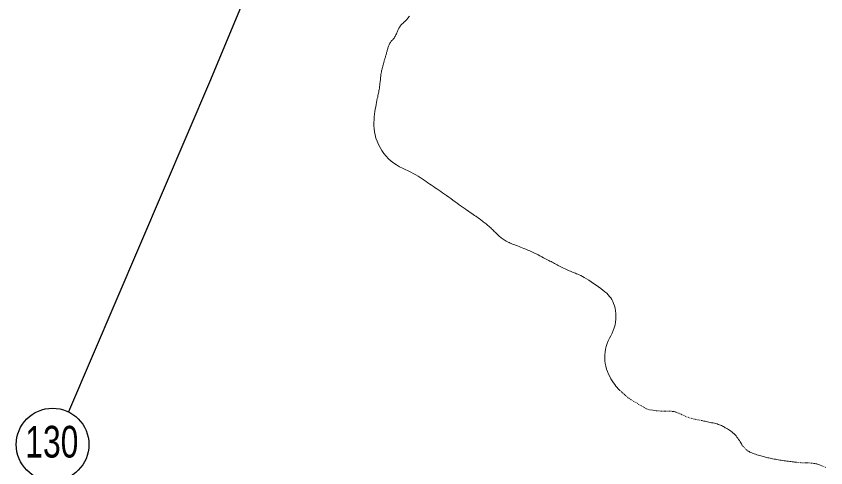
# Model space of a CAD drawing. Extents: x 553962 to 842807, y 8883888 to 9032388.
# Drawn here: x 601794 to 603582, y 8911220 to 8912217 of the extents above; entities that cross this region are included whole.
import ezdxf
from ezdxf.enums import TextEntityAlignment as Align

# ---------------------------------------------------------------- set-up
doc = ezdxf.new("R2010")
doc.units = 0
doc.header["$LTSCALE"] = 200
doc.layers.add('6', color=7, linetype='Continuous', lineweight=13)

msp = doc.modelspace()

# ---------------------------------------------------------------- linework, layer by layer
at = {"layer": '6'}
for p, q in [((602659.5, 8912214.1), (602658.3, 8912212.5)), ((602642.5, 8912196.5), (602641.7, 8912195.4)), ((602642.5, 8912196.5), (602643.4, 8912197.5)), ((602644.3, 8912198.6), (602643.4, 8912197.5)), ((602644.3, 8912198.6), (602645.3, 8912199.6)), ((602646.3, 8912200.5), (602645.3, 8912199.6)), ((602646.3, 8912200.5), (602647.3, 8912201.5)), ((602648.3, 8912202.3), (602647.3, 8912201.5)), ((602648.3, 8912202.3), (602649.2, 8912203.2)), ((602650.2, 8912204), (602649.2, 8912203.2)), ((602650.2, 8912204), (602651.1, 8912204.8)), ((602651.9, 8912205.5), (602651.1, 8912204.8)), ((602651.9, 8912205.5), (602652.7, 8912206.2)), ((602653.5, 8912207), (602652.7, 8912206.2)), ((602653.5, 8912207), (602654.4, 8912207.8)), ((602655.2, 8912208.8), (602654.4, 8912207.8)), ((602655.2, 8912208.8), (602656.2, 8912209.8)), ((602657.2, 8912211.1), (602656.2, 8912209.8)), ((602657.2, 8912211.1), (602658.3, 8912212.5)), ((602636.8, 8912186.1), (602636, 8912184.3)), ((602636.8, 8912186.1), (602637.5, 8912187.8)), ((602638.2, 8912189.3), (602637.5, 8912187.8)), ((602638.2, 8912189.3), (602638.9, 8912190.7)), ((602639.6, 8912192), (602638.9, 8912190.7)), ((602639.6, 8912192), (602640.2, 8912193.2)), ((602641, 8912194.3), (602640.2, 8912193.2)), ((602641, 8912194.3), (602641.7, 8912195.4)), ((602620.1, 8912159.3), (602621.1, 8912160.7)), ((602622.2, 8912162.1), (602621.1, 8912160.7)), ((602622.2, 8912162.1), (602623.4, 8912163.4)), ((602624.6, 8912164.8), (602623.4, 8912163.4)), ((602624.6, 8912164.8), (602625.8, 8912166.2)), ((602627, 8912167.6), (602625.8, 8912166.2)), ((602613.2, 8912142), (602613.7, 8912143.7)), ((602614.2, 8912145.5), (602613.7, 8912143.7)), ((602614.2, 8912145.5), (602614.7, 8912147.3)), ((602615.3, 8912149.1), (602614.7, 8912147.3)), ((602615.3, 8912149.1), (602615.9, 8912150.9)), ((602616.6, 8912152.7), (602615.9, 8912150.9)), ((602616.6, 8912152.7), (602617.4, 8912154.4)), ((602618.2, 8912156.1), (602617.4, 8912154.4)), ((602618.2, 8912156.1), (602619.1, 8912157.7)), ((602620.1, 8912159.3), (602619.1, 8912157.7)), ((602608.6, 8912125.6), (602608.1, 8912124.1)), ((602608.6, 8912125.6), (602609.2, 8912127.2)), ((602609.7, 8912128.8), (602609.2, 8912127.2)), ((602609.7, 8912128.8), (602610.2, 8912130.4)), ((602610.6, 8912132), (602610.2, 8912130.4)), ((602610.6, 8912132), (602611.1, 8912133.6)), ((602611.5, 8912135.3), (602611.1, 8912133.6)), ((602611.5, 8912135.3), (602611.9, 8912136.9)), ((602612.3, 8912138.6), (602611.9, 8912136.9)), ((602612.3, 8912138.6), (602612.8, 8912140.3)), ((602613.2, 8912142), (602612.8, 8912140.3)), ((602603.4, 8912106.7), (602603, 8912105.2)), ((602603.4, 8912106.7), (602603.8, 8912108.1)), ((602604.2, 8912109.7), (602603.8, 8912108.1)), ((602604.2, 8912109.7), (602604.6, 8912111.2)), ((602605, 8912112.8), (602604.6, 8912111.2)), ((602605, 8912112.8), (602605.4, 8912114.4)), ((602605.8, 8912116), (602605.4, 8912114.4)), ((602605.8, 8912116), (602606.2, 8912117.7)), ((602606.7, 8912119.3), (602606.2, 8912117.7)), ((602606.7, 8912119.3), (602607.1, 8912120.9)), ((602607.6, 8912122.5), (602607.1, 8912120.9)), ((602607.6, 8912122.5), (602608.1, 8912124.1)), ((602601.7, 8912100.7), (602601.3, 8912098.8)), ((602601.7, 8912100.7), (602602.2, 8912102.3)), ((602602.6, 8912103.8), (602602.2, 8912102.3)), ((602602.6, 8912103.8), (602603, 8912105.2)), ((603131, 8911387.2), (603129.6, 8911388.4)), ((603133.4, 8911385.2), (603132.3, 8911386.2)), ((603135.6, 8911383.3), (603134.6, 8911384.2)), ((603137.8, 8911381.3), (603136.7, 8911382.3)), ((603140, 8911379.3), (603138.9, 8911380.3)), ((603142.6, 8911377.2), (603141.3, 8911378.3)), ((603145.4, 8911374.9), (603144, 8911376.1)), ((603148.5, 8911372.6), (603147, 8911373.8)), ((603151.7, 8911370.4), (603150.1, 8911371.5)), ((603154.8, 8911368.4), (603153.2, 8911369.4)), ((603157.8, 8911366.6), (603156.3, 8911367.5)), ((603160.7, 8911364.9), (603159.2, 8911365.7)), ((603163.5, 8911363.3), (603162.1, 8911364.1)), ((603166.3, 8911361.7), (603164.9, 8911362.5)), ((603169, 8911360.1), (603167.6, 8911360.9)), ((603171.7, 8911358.5), (603170.3, 8911359.3)), ((603174.4, 8911356.9), (603173, 8911357.7)), ((603177, 8911355.3), (603175.7, 8911356.1)), ((603179.7, 8911353.8), (603178.3, 8911354.6)), ((603182.2, 8911352.4), (603180.9, 8911353.1)), ((603184.6, 8911351.1), (603183.4, 8911351.7)), ((603186.8, 8911350.1), (603185.8, 8911350.6)), ((603188.9, 8911349.3), (603187.9, 8911349.7)), ((603191, 8911348.7), (603190, 8911349)), ((603193.3, 8911348.2), (603192.2, 8911348.4)), ((603196, 8911347.7), (603194.6, 8911347.9)), ((603199.1, 8911347.2), (603197.5, 8911347.5)), ((603202.3, 8911346.8), (603200.7, 8911347)), ((603205.5, 8911346.4), (603203.9, 8911346.6)), ((603208.6, 8911346), (603207.1, 8911346.2)), ((603211.6, 8911345.7), (603210.1, 8911345.9)), ((603214.3, 8911345.5), (603213, 8911345.6)), ((603217, 8911345.3), (603215.6, 8911345.4)), ((603219.5, 8911345.2), (603218.2, 8911345.2)), ((603222, 8911345.1), (603220.8, 8911345.1)), ((603224.5, 8911345), (603223.2, 8911345.1)), ((603226.9, 8911345), (603225.7, 8911345)), ((603229.2, 8911345), (603228, 8911345)), ((603231.5, 8911345), (603230.3, 8911345)), ((603233.7, 8911344.9), (603232.6, 8911344.9)), ((603235.8, 8911344.9), (603234.8, 8911344.9)), ((603237.8, 8911344.9), (603236.8, 8911344.9)), ((603240.7, 8911344.8), (603239.7, 8911344.9)), ((603243.6, 8911344.6), (603242.6, 8911344.7)), ((603245.8, 8911344.2), (603244.7, 8911344.4)), ((603248, 8911343.7), (603246.9, 8911344)), ((603250.4, 8911343), (603249.2, 8911343.4)), ((603252.9, 8911342.1), (603251.6, 8911342.6)), ((603255.5, 8911341.1), (603254.2, 8911341.6)), ((603258.1, 8911339.9), (603256.8, 8911340.5)), ((603263.3, 8911338.7), (603259.4, 8911339.3)), ((603263.5, 8911337.3), (603262.1, 8911338)), ((603266.4, 8911336), (603265, 8911336.7)), ((603269.4, 8911334.6), (603267.9, 8911335.3)), ((603272.5, 8911333.3), (603271, 8911334)), ((603275.8, 8911332.1), (603274.1, 8911332.7)), ((603279.1, 8911330.9), (603277.4, 8911331.5)), ((603282.5, 8911329.9), (603280.8, 8911330.4)), ((603285.8, 8911329), (603284.2, 8911329.4)), ((603289.1, 8911328.2), (603287.5, 8911328.6)), ((603292.1, 8911327.5), (603290.6, 8911327.8)), ((603294.9, 8911326.9), (603293.5, 8911327.2)), ((603297.7, 8911326.3), (603296.3, 8911326.6)), ((603300.8, 8911325.7), (603299.2, 8911326)), ((603304.2, 8911325), (603302.5, 8911325.3)), ((603308.2, 8911324.2), (603306.2, 8911324.6)), ((603400, 8911266.3), (603398.8, 8911267.7)), ((603402.3, 8911263.8), (603401.2, 8911265)), ((603404.7, 8911261.5), (603403.5, 8911262.6)), ((603407.4, 8911259.2), (603406, 8911260.3)), ((603523.2, 8911231.6), (603521.3, 8911231.8)), ((603526.6, 8911231.3), (603524.9, 8911231.5)), ((603529.7, 8911231.1), (603528.2, 8911231.2)), ((603532.4, 8911231), (603531.1, 8911231.1)), ((603534.9, 8911230.9), (603533.7, 8911231)), ((603537.3, 8911230.9), (603536.1, 8911230.9)), ((603539.6, 8911230.9), (603538.5, 8911230.9)), ((603542.1, 8911230.8), (603540.8, 8911230.9)), ((603544.8, 8911230.7), (603543.4, 8911230.8)), ((603547.8, 8911230.5), (603546.2, 8911230.7)), ((603551.4, 8911230.2), (603549.6, 8911230.4)), ((603574.8, 8911223.6), (603573, 8911224.4)), ((603578.2, 8911222), (603576.5, 8911222.8)), ((603581.7, 8911220.4), (603580, 8911221.2))]:
    msp.add_line(p, q, dxfattribs=at)
at = {"layer": '6', "lineweight": 25}
msp.add_lwpolyline([(601910.1, 8911344.1), (602223.7, 8912077.8), (602313.4, 8912293.8), (602321.9, 8912321.1), (602252.1, 8912505.5), (602217.1, 8912579.8), (602219.3, 8912630.5)], dxfattribs=at)
at = {"layer": '6'}
for points in [[(602659.5, 8912214.1), (602660.8, 8912215.8), (602662.1, 8912217.6)], [(602627, 8912167.6), (602628.2, 8912169.1), (602629.4, 8912170.8), (602630.5, 8912172.6), (602631.5, 8912174.4), (602632.5, 8912176.4), (602633.5, 8912178.4), (602634.4, 8912180.5), (602635.2, 8912182.4), (602636, 8912184.3)], [(602584, 8911988.8), (602584.5, 8911995.1), (602585.1, 8912001.1), (602585.9, 8912006.8), (602586.8, 8912012.3), (602587.7, 8912017.6), (602588.6, 8912022.5), (602589.6, 8912027.1), (602590.5, 8912031.4), (602591.3, 8912035.3), (602592.1, 8912038.9), (602592.8, 8912042.1), (602593.5, 8912045.1), (602594, 8912047.8), (602594.5, 8912050.4), (602595, 8912053.1), (602595.4, 8912055.8), (602595.8, 8912058.7), (602596.2, 8912061.9), (602596.6, 8912065.4), (602597.1, 8912069.1), (602597.5, 8912073.1), (602598, 8912077.1), (602598.5, 8912081), (602598.9, 8912084.8), (602599.4, 8912088.3), (602599.9, 8912091.6), (602600.3, 8912094.3), (602600.8, 8912096.8), (602601.3, 8912098.8)], [(602744.4, 8911821.2), (602739.9, 8911824.3), (602735.6, 8911827.4), (602731.3, 8911830.3), (602727.2, 8911833.1), (602723.1, 8911835.8), (602719.1, 8911838.5), (602715.1, 8911841.2), (602711.1, 8911844), (602707.1, 8911846.8), (602703.1, 8911849.6), (602699, 8911852.5), (602694.8, 8911855.5), (602690.5, 8911858.5), (602686, 8911861.5), (602681.2, 8911864.4), (602676.2, 8911867.4), (602670.8, 8911870.2), (602665.1, 8911873), (602659.1, 8911875.8), (602652.9, 8911878.7), (602646.6, 8911881.8), (602640.2, 8911885.1), (602633.9, 8911888.8), (602627.8, 8911892.8), (602621.8, 8911897.4), (602616.2, 8911902.5), (602610.9, 8911908.1), (602605.9, 8911914.2), (602601.4, 8911920.6), (602597.3, 8911927.3), (602593.8, 8911934.1), (602590.7, 8911941.1), (602588.2, 8911948.2), (602586.4, 8911955.2), (602585.1, 8911962.2), (602584.2, 8911969), (602583.8, 8911975.8), (602583.8, 8911982.4), (602584, 8911988.8)], [(602857.3, 8911734.7), (602855.3, 8911736.5), (602853.4, 8911738.3), (602851.5, 8911740.2), (602849.6, 8911742.2), (602847.7, 8911744.1), (602845.7, 8911746), (602843.8, 8911747.9), (602841.8, 8911749.8), (602839.8, 8911751.6), (602837.8, 8911753.4), (602835.7, 8911755.2), (602833.7, 8911756.9), (602831.6, 8911758.6), (602829.5, 8911760.3), (602827.4, 8911761.9), (602825.3, 8911763.6), (602823.2, 8911765.2), (602821, 8911766.8), (602818.8, 8911768.5), (602816.6, 8911770.2), (602814.2, 8911771.9), (602811.7, 8911773.7), (602809.1, 8911775.6), (602806.2, 8911777.6), (602803.2, 8911779.7), (602800, 8911781.9), (602796.5, 8911784.2), (602792.9, 8911786.7), (602789.1, 8911789.2), (602785.1, 8911792), (602781, 8911794.8), (602776.7, 8911797.9), (602772.2, 8911801.1), (602767.7, 8911804.3), (602763, 8911807.7), (602758.4, 8911811.1), (602753.7, 8911814.5), (602749, 8911817.9), (602744.4, 8911821.2)], [(602975, 8911675.3), (602972.5, 8911676.6), (602969.9, 8911678), (602967.2, 8911679.4), (602964.4, 8911680.9), (602961.4, 8911682.4), (602958.1, 8911684.1), (602954.5, 8911686), (602950.5, 8911688), (602946.3, 8911690.1), (602941.9, 8911692.3), (602937.3, 8911694.6), (602932.7, 8911696.8), (602928.1, 8911699), (602923.6, 8911701), (602919.2, 8911702.9), (602915.2, 8911704.7), (602911.3, 8911706.2), (602907.7, 8911707.6), (602904.2, 8911708.9), (602901, 8911710.1), (602897.9, 8911711.2), (602894.9, 8911712.2), (602892.2, 8911713.3), (602889.5, 8911714.3), (602886.9, 8911715.3), (602884.5, 8911716.4), (602882.1, 8911717.4), (602879.9, 8911718.6), (602877.6, 8911719.7), (602875.5, 8911720.9), (602873.4, 8911722.2), (602871.3, 8911723.5), (602869.2, 8911724.9), (602867.2, 8911726.4), (602865.1, 8911727.9), (602863.1, 8911729.5), (602861.2, 8911731.2), (602859.2, 8911732.9), (602857.3, 8911734.7)], [(603109.2, 8911591.5), (603106.9, 8911595.2), (603104.2, 8911598.7), (603101.2, 8911602.1), (603097.8, 8911605.4), (603093.9, 8911608.7), (603089.6, 8911612.2), (603084.9, 8911615.8), (603079.7, 8911619.6), (603074.4, 8911623.4), (603068.9, 8911627.2), (603063.4, 8911630.8), (603058.1, 8911634.3), (603053.1, 8911637.4), (603048.4, 8911640.2), (603044.3, 8911642.5), (603040.6, 8911644.4), (603037.3, 8911646), (603034.3, 8911647.4), (603031.5, 8911648.6), (603028.9, 8911649.6), (603026.2, 8911650.6), (603023.6, 8911651.7), (603020.8, 8911652.8), (603017.9, 8911654), (603014.9, 8911655.3), (603011.9, 8911656.7), (603008.9, 8911658.1), (603005.8, 8911659.5), (603002.8, 8911661), (602999.7, 8911662.4), (602996.8, 8911663.9), (602993.8, 8911665.4), (602991, 8911666.8), (602988.2, 8911668.3), (602985.5, 8911669.7), (602982.8, 8911671.1), (602980.1, 8911672.5), (602977.5, 8911673.9), (602975, 8911675.3)], [(603128.2, 8911389.7), (603126.5, 8911391.1), (603124.8, 8911392.9), (603122.8, 8911394.9), (603120.6, 8911397.4), (603118.3, 8911400.3), (603115.7, 8911403.7), (603113, 8911407.5), (603110.1, 8911411.8), (603107.3, 8911416.5), (603104.6, 8911421.5), (603102, 8911426.8), (603099.7, 8911432.4), (603097.7, 8911438.2), (603096, 8911444.2), (603094.8, 8911450.4), (603094, 8911456.6), (603093.6, 8911463), (603093.7, 8911469.3), (603094.2, 8911475.7), (603095.3, 8911481.9), (603096.9, 8911488.1), (603099, 8911494.2), (603101.4, 8911500.1), (603104.1, 8911506), (603106.9, 8911511.8), (603109.7, 8911517.7), (603112.3, 8911523.6), (603114.5, 8911529.5), (603116.3, 8911535.6), (603117.5, 8911541.9), (603118.2, 8911548.2), (603118.3, 8911554.5), (603118, 8911560.7), (603117.3, 8911566.7), (603116.2, 8911572.5), (603114.8, 8911577.9), (603113.2, 8911582.9), (603111.3, 8911587.4), (603109.2, 8911591.5)], [(603397.7, 8911269.3), (603396.5, 8911271), (603395.2, 8911273), (603393.8, 8911275.2), (603392.4, 8911277.6), (603390.8, 8911280.1), (603389.2, 8911282.7), (603387.4, 8911285.3), (603385.5, 8911287.9), (603383.5, 8911290.4), (603381.4, 8911292.9), (603379.1, 8911295.2), (603376.7, 8911297.3), (603374.3, 8911299.2), (603371.8, 8911301.1), (603369.3, 8911302.8), (603366.8, 8911304.4), (603364.4, 8911305.9), (603362, 8911307.3), (603359.8, 8911308.6), (603357.7, 8911309.8), (603355.6, 8911311), (603353.5, 8911312.1), (603351.4, 8911313.1), (603349.1, 8911314.1), (603346.8, 8911315), (603344.3, 8911315.9), (603341.6, 8911316.8), (603338.7, 8911317.6), (603335.7, 8911318.3), (603332.7, 8911319), (603329.6, 8911319.7), (603326.5, 8911320.4), (603323.5, 8911321), (603320.6, 8911321.6), (603317.8, 8911322.2), (603315.2, 8911322.7), (603312.7, 8911323.2), (603310.4, 8911323.7), (603308.2, 8911324.2)], [(603412.3, 8911255.9), (603410.6, 8911257), (603408.9, 8911258.1)], [(603519.3, 8911232), (603517.2, 8911232.3), (603515, 8911232.5), (603512.6, 8911232.8), (603510.1, 8911233.1), (603507.5, 8911233.4), (603504.8, 8911233.7), (603501.9, 8911234.1), (603498.9, 8911234.4), (603495.9, 8911234.8), (603492.8, 8911235.2), (603489.6, 8911235.7), (603486.4, 8911236.1), (603483.2, 8911236.6), (603479.9, 8911237.1), (603476.7, 8911237.7), (603473.5, 8911238.2), (603470.3, 8911238.8), (603467.3, 8911239.3), (603464.3, 8911239.9), (603461.5, 8911240.5), (603458.7, 8911241.1), (603456.1, 8911241.7), (603453.6, 8911242.3), (603451.1, 8911242.9), (603448.6, 8911243.5), (603446.1, 8911244.2), (603443.5, 8911244.8), (603440.8, 8911245.6), (603438.1, 8911246.3), (603435.2, 8911247.2), (603432.3, 8911248), (603429.4, 8911248.9), (603426.5, 8911249.8), (603423.8, 8911250.8), (603421.1, 8911251.7), (603418.6, 8911252.8), (603416.3, 8911253.8), (603414.2, 8911254.8), (603412.3, 8911255.9)], [(603571.2, 8911225.2), (603569.3, 8911226), (603567.5, 8911226.7), (603565.6, 8911227.4), (603563.6, 8911228), (603561.6, 8911228.6), (603559.5, 8911229), (603557.4, 8911229.4), (603555.4, 8911229.7), (603553.4, 8911230)]]:
    msp.add_lwpolyline(points, dxfattribs=at)
at = {"layer": '6', "lineweight": 25}
msp.add_circle((601874.1, 8911271.4), 80.3, dxfattribs=at)

# ---------------------------------------------------------------- texts
at = {"layer": '6', "width": 0.75}
msp.add_text('130', height=70, dxfattribs=at).set_placement((601872.6, 8911242.7), align=Align.CENTER)

doc.saveas('drawing.dxf')
